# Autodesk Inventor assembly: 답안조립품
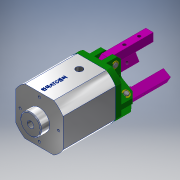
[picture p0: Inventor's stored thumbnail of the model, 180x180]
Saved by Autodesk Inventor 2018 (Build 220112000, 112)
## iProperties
Created: 2020-02
Part Number: 답안조립품
Material: 일반
Document SubType Name: Assembly
Designer: USER
Author: USER
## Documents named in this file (13)
- C:\Users\USER\Desktop\700206V1017\답안조립품.iam
- C:\Users\USER\Desktop\700206V1017\본체.ipt
- C:\Users\USER\Desktop\700206V1017\E링.ipt
- C:\Users\USER\Desktop\700206V1017\O-RING 12x16.ipt
- C:\Users\USER\Desktop\700206V1017\O-RING 18x22.ipt
- C:\Users\USER\Desktop\700206V1017\O-RING 34x40.ipt
- C:\Users\USER\Desktop\700206V1017\로드.ipt
- C:\Users\USER\Desktop\700206V1017\본체헤드.ipt
- C:\Users\USER\Desktop\700206V1017\볼트 M4.ipt
- C:\Users\USER\Desktop\700206V1017\피스톤.ipt
- C:\Users\USER\Desktop\700206V1017\핀 A.ipt
- C:\Users\USER\Desktop\700206V1017\핀 B.ipt
- C:\Users\USER\Desktop\700206V1017\핑거.ipt
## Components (20 placed, 8 different names)
1. E링:1
2. O-RING 12x16:1
3. O-RING 18x22:1
4. O-RING 34x40:1
5. 피스톤:1
6. 핀 A:1
7. 핀 B:1
8. 핑거:1
9. O-RING 34x40:2
10. 핀 A:2
11. 핀 A:3
12. E링:2
13. E링:3
14. E링:4
15. E링:5
16. E링:6
17. 핀 B:2
18. 핑거:2
19. 핀 B:3
20. 핑거:3
## Named parameters: d24_d23 = 0, d25_d23 = 0
